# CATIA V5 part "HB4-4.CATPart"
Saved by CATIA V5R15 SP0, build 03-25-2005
Part number: SB2_04.2
Bounding box of the stored display mesh (mm): x -158 to 0, y 0 to 316, z 0 to 47
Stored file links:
  E:\#01 CATIA Lecture Materials\#06 DMU\#11 DMU Page01 KIN EX11\HB4-4.CATPart
  C:\Documents and Settings\c-cap\My Documents\정욱순\레고\SB2-16.CATPart
  E:\공학과제\SB2_04_02.CATPart
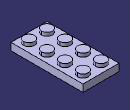
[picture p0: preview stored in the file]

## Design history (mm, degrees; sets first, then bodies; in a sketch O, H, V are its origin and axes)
Body1 (main body)
  Sketch1 on zx-plane, origin (0, 0, 0), H (-1, 0, 0), V (0, 0, 1)
    point P1 (0, 32)
    line L1 (0, 32) -> (158, 32)
    line L2 (158, 32) -> (158, 0)
    line L3 (158, 0) -> (0, 0)
    line L4 (0, 0) -> (0, 32)
    point P3 (158, 0)
    distance L2 L4 = 158
    length L2 = 32
    coincidence: P1 V, P3 H
    horizontal: L1 H, L3 H
    vertical: L2 V, L4 V
  Pad1: profile Sketch1, direction (0, 1, 0), length 316
  Sketch2 on xy-plane, origin (0, 0, 0), H (1, 0, 0), V (0, 1, 0)
    circle A1 centre (-39.5, 39.5) radius 23.5
    point P1 (-39.5, 39.5)
    reference projected line E1 (0, 0) -> (0, 316) from edge [face of Pad1 from Sketch1.L4 | face of Pad1 from Sketch1.L1]
    reference projected line E2 (-158, 0) -> (0, 0) from edge [start face of Pad1 | face of Pad1 from Sketch1.L1]
    radius A1 = 23.5
    distance P1 E1 = 39.5
    distance P1 E2 = 39.5
  Pad2: profile Sketch2, direction (0, 0, 1), length 47
  RectPattern1: of Pad2, direction 1 instances 2, spacing 79, along xy-plane reversed, direction 2 instances 4, spacing 79, along xy-plane
  Shell1: ExtOffset 0, Face face of Pad2, IntOffset 15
